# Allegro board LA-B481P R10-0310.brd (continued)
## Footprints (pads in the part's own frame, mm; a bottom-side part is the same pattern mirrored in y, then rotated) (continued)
FIDUCIAL_C40M80
  round 1.016 smd: 1(0,0)
G993P1UF_SOP8
  oval 0.635x1.854 smd: 1(0,0) 2(1.27,0) 3(2.54,0) 4(3.81,0) 5(3.81,5.165) 6(2.54,5.165) 7(1.27,5.165) 8(0,5.165)
G2129TL1U_SC70-6
  oval 0.305x0.711 smd: 1(0,0) 2(0.65,0) 3(1.3,0) 4(1.3,2.15) 5(0.65,2.15) 6(0,2.15)
H_2P8
  round 3.302 hole 2.794: 1(0,0)
H_3P3
  round 3.81 hole 3.302: 1(0,0)
H_3P7
  round 4.216 hole 3.708: 1(0,0)
H_3P7X3P2N
  oval 3.708x3.2 hole 3.708x3.2 unplated: (0,0)
HB_A090420-SAHR21_4P
  oval 0.61x1.499 smd: 1(0,0) 2(1,0) 3(2,0) 4(3,0)
  rect 2.489x2.21 smd: 5(-3,-3.15) 6(6,-3.15)
HB_A823020-SBHR21_30P
  oval 0.305x1.295 smd: 1(0,0) 2(0.8,0) 3(1.6,0) 4(2.4,0) 5(3.2,0) 6(4,0) 7(4.8,0) 8(5.6,0) 9(6.4,0) 10(7.2,0) 11(8,0) 12(8.8,0) 13(9.6,0) 14(10.4,0) 15(11.2,0) 16(12,0) 17(12.8,0) 18(13.6,0) 19(14.4,0) 20(15.2,0) 21(16,0) 22(16.8,0) 23(17.6,0) 24(18.4,0) 25(19.2,0) 26(20,0) 27(20.8,0) 28(21.6,0) 29(22.4,0) 30(23.2,0)
  rect 1.803x2.21 smd: 31(25.55,-5.65) 32(-2.35,-5.65)
IP4292CZ10-TBR_XSON10_2P5X1
  oval 0.254x0.889 smd: 1(0,0)
  oval 0.254x0.838 smd: 2(0.5,-0.025) 3(1,-0.025) 4(1.5,-0.025) 5(2,-0.025) 6(2,1.125) 7(1.5,1.125) 8(1,1.125) 9(0.5,1.125) 10(0,1.125)
ISL95833HRTZ-T_TQFN32_4X4
  oval 0.203x0.914 smd: 1(0,0) 2(0.4,0) 3(0.8,0) 4(1.2,0) 5(1.6,0) 6(2,0) 7(2.4,0) 8(2.8,0) 17(2.8,4.077) 18(2.4,4.077) 19(2,4.077) 20(1.6,4.077) 21(1.2,4.077) 22(0.8,4.077) 23(0.4,4.077) 24(0,4.077)
  oval 0.914x0.203 smd: 9(3.438,0.639) 10(3.438,1.039) 11(3.438,1.438) 12(3.438,1.838) 13(3.438,2.239) 14(3.438,2.639) 15(3.438,3.039) 16(3.438,3.438) 25(-0.639,3.438) 26(-0.639,3.039) 27(-0.639,2.639) 28(-0.639,2.239) 29(-0.639,1.838) 30(-0.639,1.438) 31(-0.639,1.039) 32(-0.639,0.639)
  rect 2.692x2.692 smd: 33(1.4,2.039)
JUMP_43X39
  custom 0.191x0.191 smd: 1(0,0) 2(0.914,0)
JUMP_43X79
  custom 0.188x0.188 smd: 1(0,0) 2(1.1,0)
JUMP_43X118
  custom 0.187x0.187 smd: 1(0,0) 2(1.1,0)
KB9012QF-A2_LQFP128_14X14
  oval 0.203x1.753 smd: 1(0,0) 2(0.4,0) 3(0.8,0) 4(1.2,0) 5(1.6,0) 6(2,0) 7(2.4,0) 8(2.8,0) 9(3.2,0) 10(3.6,0) 11(4,0) 12(4.4,0) 13(4.8,0) 14(5.2,0) 15(5.6,0) 16(6,0) 17(6.4,0) 18(6.8,0) 19(7.2,0) 20(7.6,0) 21(8,0) 22(8.4,0) 23(8.8,0) 24(9.2,0) 25(9.6,0) 26(10,0) 27(10.4,0) 28(10.8,0) 29(11.2,0) 30(11.6,0) 31(12,0) 32(12.4,0) 65(12.4,15.654) 66(12,15.654) 67(11.6,15.654) 68(11.2,15.654) 69(10.8,15.654) 70(10.4,15.654) 71(10,15.654) 72(9.6,15.654) 73(9.2,15.654) 74(8.8,15.654) 75(8.4,15.654) 76(8,15.654) 77(7.6,15.654) 78(7.2,15.654) 79(6.8,15.654) 80(6.4,15.654) 81(6,15.654) 82(5.6,15.654) 83(5.2,15.654) 84(4.8,15.654) 85(4.4,15.654) 86(4,15.654) 87(3.6,15.654) 88(3.2,15.654) 89(2.8,15.654) 90(2.4,15.654) 91(2,15.654) 92(1.6,15.654) 93(1.2,15.654) 94(0.8,15.654) 95(0.4,15.654) 96(0,15.654)
  oval 1.753x0.203 smd: 33(14.027,1.627) 34(14.027,2.027) 35(14.027,2.427) 36(14.027,2.827) 37(14.027,3.227) 38(14.027,3.627) 39(14.027,4.027) 40(14.027,4.427) 41(14.027,4.827) 42(14.027,5.227) 43(14.027,5.627) 44(14.027,6.027) 45(14.027,6.427) 46(14.027,6.827) 47(14.027,7.227) 48(14.027,7.627) 49(14.027,8.027) 50(14.027,8.427) 51(14.027,8.827) 52(14.027,9.227) 53(14.027,9.627) 54(14.027,10.027) 55(14.027,10.427) 56(14.027,10.827) 57(14.027,11.227) 58(14.027,11.627) 59(14.027,12.027) 60(14.027,12.427) 61(14.027,12.827) 62(14.027,13.227) 63(14.027,13.627) 64(14.027,14.027) 97(-1.627,14.027) 98(-1.627,13.627) 99(-1.627,13.227) 100(-1.627,12.827) 101(-1.627,12.427) 102(-1.627,12.027) 103(-1.627,11.627) 104(-1.627,11.227) 105(-1.627,10.827) 106(-1.627,10.427) 107(-1.627,10.027) 108(-1.627,9.627) 109(-1.627,9.227) 110(-1.627,8.827) 111(-1.627,8.427) 112(-1.627,8.027) 113(-1.627,7.627) 114(-1.627,7.227) 115(-1.627,6.827) 116(-1.627,6.427) 117(-1.627,6.027) 118(-1.627,5.627) 119(-1.627,5.227) 120(-1.627,4.827) 121(-1.627,4.427) 122(-1.627,4.027) 123(-1.627,3.627) 124(-1.627,3.227) 125(-1.627,2.827) 126(-1.627,2.427) 127(-1.627,2.027) 128(-1.627,1.627)
KC_FBMA-L11-160808-800LMT_2P
  rect 0.889x1.092 smd: 1(0,0) 2(1.5,0)
KC_FBMA-L11-201209-221LMA30_2P
  rect 0.838x1.397 smd: 1(0,0) 2(1.65,0)
KC_WCM-2012HS-900T_4P
  rect 0.889x0.406 smd: 1(0,0) 2(1.7,0) 3(1.7,-0.8) 4(0,-0.8)
L03ESDL5V0CG3-2_SOT-523-3
  oval 0.406x0.787 smd: 1(0,0) 2(-0.5,-1.4) 3(0.5,-1.4)
L30ESDL5V0C3-2_SOT23-3
  oval 1.016x1.524 smd: 1(0,0) 2(0.965,2.083) 3(-0.965,2.083)
L_4X4X2_F_2P
  rect 1.194x3.708 smd: 1(0,0) 2(2.8,0)
L_5X5X3_M_2P
  rect 2.159x2.794 smd: 1(0,0) 2(4.35,0)
L_7X7X3_M_2P
  rect 2.362x3.505 smd: 1(0,0) 2(6.05,0)
LCN_DAN06-K4406-0102_204P
  round 1.6 hole 1.6 unplated: (-1.75,4.1)
  round 1.092 hole 1.092 unplated: (65.05,4.1)
  oval 0.356x2.007 smd: 1(0,0) 2(0.3,8.2) 3(0.6,0) 4(0.9,8.2) 5(1.2,0) 6(1.5,8.2) 7(1.8,0) 8(2.1,8.2) 9(2.4,0) 10(2.7,8.2) 11(3,0) 12(3.3,8.2) 13(3.6,0) 14(3.9,8.2) 15(4.2,0) 16(4.5,8.2) 17(4.8,0) 18(5.1,8.2) 19(5.4,0) 20(5.7,8.2) 21(6,0) 22(6.3,8.2) 23(6.6,0) 24(6.9,8.2) 25(7.2,0) 26(7.5,8.2) 27(7.8,0) 28(8.1,8.2) 29(8.4,0) 30(8.7,8.2) 31(9,0) 32(9.3,8.2) 33(9.6,0) 34(9.9,8.2) 35(10.2,0) 36(10.5,8.2) 37(10.8,0) 38(11.1,8.2) 39(11.4,0) 40(11.7,8.2) 41(12,0) 42(12.3,8.2) 43(12.6,0) 44(12.9,8.2) 45(13.2,0) 46(13.5,8.2) 47(13.8,0) 48(14.1,8.2) 49(14.4,0) 50(14.7,8.2) 51(15,0) 52(15.3,8.2) 53(15.6,0) 54(15.9,8.2) 55(16.2,0) 56(16.5,8.2) 57(16.8,0) 58(17.1,8.2) 59(17.4,0) 60(17.7,8.2) 61(18,0) 62(18.3,8.2) 63(18.6,0) 64(18.9,8.2) 65(19.2,0) 66(19.5,8.2) 67(19.8,0) 68(20.1,8.2) 69(20.4,0) 70(20.7,8.2) 71(21,0) 72(21.3,8.2) 73(24,0) 74(24.3,8.2) 75(24.6,0) 76(24.9,8.2) 77(25.2,0) 78(25.5,8.2) 79(25.8,0) 80(26.1,8.2) 81(26.4,0) 82(26.7,8.2) 83(27,0) 84(27.3,8.2) 85(27.6,0) 86(27.9,8.2) 87(28.2,0) 88(28.5,8.2) 89(28.8,0) 90(29.1,8.2) 91(29.4,0) 92(29.7,8.2) 93(30,0) 94(30.3,8.2) 95(30.6,0) 96(30.9,8.2) 97(31.2,0) 98(31.5,8.2) 99(31.8,0) 100(32.1,8.2) 101(32.4,0) 102(32.7,8.2) 103(33,0) 104(33.3,8.2) 105(33.6,0) 106(33.9,8.2) 107(34.2,0) 108(34.5,8.2) 109(34.8,0) 110(35.1,8.2) 111(35.4,0) 112(35.7,8.2) 113(36,0) 114(36.3,8.2) 115(36.6,0) 116(36.9,8.2) 117(37.2,0) 118(37.5,8.2) 119(37.8,0) 120(38.1,8.2) 121(38.4,0) 122(38.7,8.2) 123(39,0) 124(39.3,8.2) 125(39.6,0) 126(39.9,8.2) 127(40.2,0) 128(40.5,8.2) 129(40.8,0) 130(41.1,8.2) 131(41.4,0) 132(41.7,8.2) 133(42,0) 134(42.3,8.2) 135(42.6,0) 136(42.9,8.2) 137(43.2,0) 138(43.5,8.2) 139(43.8,0) 140(44.1,8.2) 141(44.4,0) 142(44.7,8.2) 143(45,0) 144(45.3,8.2) 145(45.6,0) 146(45.9,8.2) 147(46.2,0) 148(46.5,8.2) 149(46.8,0) 150(47.1,8.2) 151(47.4,0) 152(47.7,8.2) 153(48,0) 154(48.3,8.2) 155(48.6,0) 156(48.9,8.2) 157(49.2,0) 158(49.5,8.2) 159(49.8,0) 160(50.1,8.2) 161(50.4,0) 162(50.7,8.2) 163(51,0) 164(51.3,8.2) 165(51.6,0) 166(51.9,8.2) 167(52.2,0) 168(52.5,8.2) 169(52.8,0) 170(53.1,8.2) 171(53.4,0) 172(53.7,8.2) 173(54,0) 174(54.3,8.2) 175(54.6,0) 176(54.9,8.2) 177(55.2,0) 178(55.5,8.2) 179(55.8,0) 180(56.1,8.2) 181(56.4,0) 182(56.7,8.2) 183(57,0) 184(57.3,8.2) 185(57.6,0) 186(57.9,8.2) 187(58.2,0) 188(58.5,8.2) 189(58.8,0) 190(59.1,8.2) 191(59.4,0) 192(59.7,8.2) 193(60,0) 194(60.3,8.2) 195(60.6,0) 196(60.9,8.2) 197(61.2,0) 198(61.5,8.2) 199(61.8,0) 200(62.1,8.2) 201(62.4,0) 202(62.7,8.2) 203(63,0) 204(63.3,8.2)
  rect 3.505x4.597 smd: 205(-1.15,16.1) 206(64.45,16.1)
LED_12-21C-T3D-CM2P1B18X-2C_3P
  rect 0.991x0.787 smd: 1(0,0) 2(-2.8,0)
  rect 0.991x0.61 smd: 3(-1.4,0.4)
LED_HT-210UD5-BP5_3P
  rect 1.194x0.787 smd: 1(0,0) 2(3,0)
  rect 0.889x0.991 smd: 3(1.5,0.5)
LOTES_AAA-BAT-054-K01_2P
  round 0.787 hole 0.787 unplated: (-14.5,-8)
  round 1.194 hole 1.194 unplated: (-14.5,8)
  rect 2.007x3.988 smd: 1(0,0) 2(-30.1,0)
LOTES_ABA-HDM-022-K01_19P
  round 0.813 hole 0.559: 1(0,0) 2(-0.5,-1.55) 3(-1,0) 4(-1.5,-1.55) 5(-2,0) 6(-2.5,-1.55) 7(-3,0) 8(-3.5,-1.55) 9(-4,0) 10(-4.5,-1.55) 11(-5,0) 12(-5.5,-1.55) 13(-6,0) 14(-6.5,-1.55) 15(-7,0) 16(-7.5,-1.55) 17(-8,0) 18(-8.5,-1.55) 19(-9,0)
  oval 1.702x2.794 hole 1.092x2.21: 20(4.55,5.38) 21(4.55,-1.72) 22(-13.55,-1.72) 23(-13.55,5.38)
MC74VHC1G08DFT2G_SC70-5
  oval 0.381x0.711 smd: 1(0,0) 2(0.65,0) 3(1.3,0) 4(1.3,1.9) 5(0,1.9)
MDS1525URH_SO8
  oval 0.635x1.854 smd: 1(0,0) 2(1.27,0) 3(2.54,0) 4(3.81,0) 5(3.81,5.165) 6(2.54,5.165) 7(1.27,5.165) 8(0,5.165)
MDV1527URH_POWERDFN33-8-5
  oval 0.406x0.61 smd: 1(0,0) 2(0.65,0) 3(1.3,0) 4(1.95,0)
  custom 0.65x0.65 smd: 5(0.975,1.475)
MDV1528URH_PDFN33-8-5
  oval 0.406x0.61 smd: 1(0,0) 2(0.65,0) 3(1.3,0) 4(1.95,0)
  custom 0.65x0.65 smd: 5(0.975,1.475)
MESS138W-G_SOT323-3
  oval 0.711x0.889 smd: 1(0,0) 2(-0.65,-1.9) 3(0.65,-1.9)
MOLEX_52435-2671_26P-T
  oval 0.305x0.787 smd: 1(0,0) 2(0.5,0) 3(1,0) 4(1.5,0) 5(2,0) 6(2.5,0) 7(3,0) 8(3.5,0) 9(4,0) 10(4.5,0) 11(5,0) 12(5.5,0) 13(6,0) 14(6.5,0) 15(7,0) 16(7.5,0) 17(8,0) 18(8.5,0) 19(9,0) 20(9.5,0) 21(10,0) 22(10.5,0) 23(11,0) 24(11.5,0) 25(12,0) 26(12.5,0)
  custom 0.597x0.597 smd: 27(-2.45,-1.925) 28(14.95,-1.925)
MURAT_BLM15AG601SN1D_2P
  oval 0.457x0.508 smd: 1(0,0) 2(0.85,0)
MURAT_BLM15BB221SN1D_2P
  rect 0.508x0.762 smd: 1(0,0) 2(0.75,0)
MURAT_BLM15BX102SN1D_2P
  rect 0.457x0.508 smd: 1(0,0) 2(0.85,0)
MURAT_DLW21SN670HQ2L_4P
  rect 0.889x0.406 smd: 1(0,0) 2(1.7,0) 3(1.7,0.8) 4(0,0.8)
PANAS_ETQP4LR15AFM_4P
  custom 0.686x0.686 smd: 1(0,0) 4(8.357,0)
  rect 2.21x0.508 smd: 2(1.448,0) 3(6.909,0)
PESD5V0U2BT_SOT23-3
  oval 1.016x1.524 smd: 1(0,0) 2(0.965,2.083) 3(-0.965,2.083)
PS_HPF10052-06M000R_6P
  oval 0.305x1.499 smd: 1(0,0) 2(1,0) 3(2,0) 4(3,0) 5(4,0) 6(5,0)
  rect 2.489x1.905 smd: 7(7.65,-3.4) 8(-2.65,-3.4)
R0402_0OHM
  rect 0.508x0.559 smd: 1(0,0) 2(0.914,0)
R0603_0OHM
  rect 0.635x0.889 smd: 1(0,0) 2(1.397,0)
R0805_0OHM
  rect 0.813x1.397 smd: 1(0,0) 2(1.702,0)
R_0402
  rect 0.508x0.559 smd: 1(0,0) 2(0.914,0)
R_0603
  rect 0.635x0.889 smd: 1(0,0) 2(1.397,0)
R_0805
  rect 0.813x1.397 smd: 1(0,0) 2(1.702,0)
R_1206
  rect 1.016x1.651 smd: 1(0,0) 2(2.667,0)
R_1206_4P-D
  custom 0.445x0.445 smd: 1(0,0) 4(5.004,0)
  custom 0.114x0.114 smd: 2(1.194,0) 3(3.81,0)
RB751V40_SC76-2
  rect 0.61x0.61 smd: 1(0,0) 2(2.2,0)
RB751V-40_SOD323-2
  rect 0.787x0.889 smd: 1(0,0) 2(2.14,0)
RHU002N06_SOT323-3
  oval 0.813x0.914 smd: 1(0,0) 2(0.65,1.6) 3(-0.65,1.6)
RP_0804_8P4R
  oval 0.66x0.254 smd: 1(0,0) 2(0,-0.5) 3(0,-1) 4(0,-1.5) 5(1.15,-1.5) 6(1.15,-1) 7(1.15,-0.5) 8(1.15,0)
RT8207MZQW_WQFN20_3X3
  oval 0.203x0.889 smd: 1(0,0) 2(0.4,0) 3(0.8,0) 4(1.2,0) 5(1.6,0) 11(1.6,3.1) 12(1.2,3.1) 13(0.8,3.1) 14(0.4,3.1) 15(0,3.1)
  oval 0.889x0.203 smd: 6(2.35,0.75) 7(2.35,1.15) 8(2.35,1.55) 9(2.35,1.95) 10(2.35,2.35) 16(-0.75,2.35) 17(-0.75,1.95) 18(-0.75,1.55) 19(-0.75,1.15) 20(-0.75,0.75)
  rect 1.702x1.702 smd: 21(0.8,1.55)
RTD2132S-GR_QFN32_5X5
  oval 0.254x1.041 smd: 1(0,0) 2(0.5,0) 3(1,0) 4(1.5,0) 5(2,0) 6(2.5,0) 7(3,0) 8(3.5,0) 17(3.5,4.95) 18(3,4.95) 19(2.5,4.95) 20(2,4.95) 21(1.5,4.95) 22(1,4.95) 23(0.5,4.95) 24(0,4.95)
  oval 1.041x0.254 smd: 9(4.225,0.725) 10(4.225,1.225) 11(4.225,1.725) 12(4.225,2.225) 13(4.225,2.725) 14(4.225,3.225) 15(4.225,3.725) 16(4.225,4.225) 25(-0.725,4.225) 26(-0.725,3.725) 27(-0.725,3.225) 28(-0.725,2.725) 29(-0.725,2.225) 30(-0.725,1.725) 31(-0.725,1.225) 32(-0.725,0.725)
  rect 3.353x3.353 smd: 33(1.75,2.475)
RTL8106E-CG_QFN32_4X4
  oval 0.203x0.838 smd: 1(0,0) 2(0.4,0) 3(0.8,0) 4(1.2,0) 5(1.6,0) 6(2,0) 7(2.4,0) 8(2.8,0) 17(2.8,4.15) 18(2.4,4.15) 19(2,4.15) 20(1.6,4.15) 21(1.2,4.15) 22(0.8,4.15) 23(0.4,4.15) 24(0,4.15)
  oval 0.838x0.203 smd: 9(3.475,0.675) 10(3.475,1.075) 11(3.475,1.475) 12(3.475,1.875) 13(3.475,2.275) 14(3.475,2.675) 15(3.475,3.075) 16(3.475,3.475) 25(-0.675,3.475) 26(-0.675,3.075) 27(-0.675,2.675) 28(-0.675,2.275) 29(-0.675,1.875) 30(-0.675,1.475) 31(-0.675,1.075) 32(-0.675,0.675)
  rect 2.692x2.692 smd: 33(1.4,2.075)
RTS5179-GR_QFN24_4X4
  oval 0.254x0.889 smd: 1(0,0) 2(0.5,0) 3(1,0) 4(1.5,0) 5(2,0) 6(2.5,0) 13(2.5,4.1) 14(2,4.1) 15(1.5,4.1) 16(1,4.1) 17(0.5,4.1) 18(0,4.1)
  oval 0.889x0.254 smd: 7(3.3,0.8) 8(3.3,1.3) 9(3.3,1.8) 10(3.3,2.3) 11(3.3,2.8) 12(3.3,3.3) 19(-0.8,3.3) 20(-0.8,2.8) 21(-0.8,2.3) 22(-0.8,1.8) 23(-0.8,1.3) 24(-0.8,0.8)
  rect 2.261x2.261 smd: 25(1.25,2.05)
SANTA_130456-311_8P
  round 1.295 hole 0.889: 1(0,0) 2(1.02,1.1) 3(2.04,0) 4(3.06,1.1) 5(4.08,0) 6(5.1,1.1) 7(6.12,0) 8(7.14,1.1)
  oval 1.753x3.15 hole 0.991x2.388: 9(-5.83,-12) 10(12.97,-12)
SANTA_193202-1_22P
  round 1.194 hole 1.194 unplated: (-31.47,-1.84) (-0.28,-1.84)
  round 1.092 hole 0.787: 1(0,0) 2(-1.27,0) 3(-2.54,0) 4(-3.81,0) 5(-5.08,0) 6(-6.35,0) 7(-7.62,0) 8(-13.97,0) 9(-15.24,0) 10(-16.51,0) 11(-17.78,0) 12(-19.05,0) 13(-20.32,0) 14(-21.59,0) 15(-22.86,0) 16(-24.13,0) 17(-25.4,0) 18(-26.67,0) 19(-27.94,0) 20(-29.21,0) 21(-30.48,0) 22(-31.75,0)
  oval 1.803x3.2 hole 0.991x2.388: 23(2.2,-0.73) 24(-33.95,-0.73)
SANTA_202801-1_13P
  round 1.194 hole 1.194 unplated: (-19.78,-1.75) (1.02,-1.75)
  round 1.067 hole 0.711: 1(0,0) 2(-1.27,0) 3(-2.54,0) 4(-3.81,0) 5(-5.08,0) 6(-6.35,0) 7(-7.62,0)
  round 1.016 hole 0.61: 8(-13.83,1) 9(-14.83,0) 10(-15.83,1) 11(-16.83,0) 12(-17.83,1) 13(-18.83,0)
  custom 1.499x1.499 hole 2.311: 14(3.77,-0.75) 15(-22.53,-0.75)
SHORTPADS
  custom 0.19x0.19 smd: 1(-0.483,0) 2(0.483,0)
SI3456BDV-T1-E3_TSOP6
  oval 0.508x1.448 smd: 1(0,0) 2(1,0) 3(2,0) 4(2,2.425) 5(1,2.425) 6(0,2.425)
SI3457CDV-T1-GE3_TSOP6
  oval 0.508x1.422 smd: 1(0,0) 2(0.95,0) 3(1.9,0) 4(1.9,2.44) 5(0.95,2.44) 6(0,2.44)
SI4459ADY-T1-GE3_SO8
  oval 0.635x1.727 smd: 1(0,0) 2(1.27,0) 3(2.54,0) 4(3.81,0) 5(3.81,5.285) 6(2.54,5.285) 7(1.27,5.285) 8(0,5.285)
SINGA_2SJ-E960-001F_6P
  oval 1.194x1.803 hole 0.61x1.194: 1(0,0) 2(11.8,0) 3(0,-9.65) 4(11.8,-2.5) 5(11.8,-9.65) 6(0,-5.62)
SLG3NB274VTR_TQFN16_2X3
  oval 0.203x0.914 smd: 1(0,-0.013) 2(0.4,-0.013) 3(0.8,-0.013) 4(1.2,-0.013) 5(1.6,-0.013) 6(2,-0.013) 7(2.4,-0.013) 9(2.4,2.063) 10(2,2.063) 11(1.6,2.063) 12(1.2,2.063) 13(0.8,2.063) 14(0.4,2.063) 15(0,2.063)
  oval 0.914x0.203 smd: 8(2.738,1.025) 16(-0.338,1.025)
  rect 1.905x0.889 smd: 17(1.2,1.025)
SN74LVC1G06DCKR_SC70-5
  oval 0.381x0.864 smd: 1(0,0) 2(0.65,0) 3(1.3,0) 4(1.3,1.74) 5(0,1.74)
SN74LVC1G07DCKR_SC70-5
  oval 0.381x0.864 smd: 1(0,0) 2(0.65,0) 3(1.3,0) 4(1.3,1.74) 5(0,1.74)
STARC_107K40-000001-G2_40P
  round 1.092 hole 1.092 unplated: (-2.3,-1.95) (21.8,-1.95)
  oval 0.254x1.295 smd: 1(0,0) 2(0.5,0) 3(1,0) 4(1.5,0) 5(2,0) 6(2.5,0) 7(3,0) 8(3.5,0) 9(4,0) 10(4.5,0) 11(5,0) 12(5.5,0) 13(6,0) 14(6.5,0) 15(7,0) 16(7.5,0) 17(8,0) 18(8.5,0) 19(9,0) 20(9.5,0) 21(10,0) 22(10.5,0) 23(11,0) 24(11.5,0) 25(12,0) 26(12.5,0) 27(13,0) 28(13.5,0) 29(14,0) 30(14.5,0) 31(15,0) 32(15.5,0) 33(16,0) 34(16.5,0) 35(17,0) 36(17.5,0) 37(18,0) 38(18.5,0) 39(19,0) 40(19.5,0)
  rect 1.549x3.404 smd: 41(-4.125,-5.85) 42(23.625,-5.85)
  rect 2.007x6.198 smd: 43(0.5,-7.65) 44(6,-7.65) 45(13.5,-7.65) 46(19,-7.65)
SUYIN_200028MR009G502ZL_9P
  round 1.499 hole 0.991: 1(0,0) 2(2,0) 3(4,0) 4(6,0) 5(8,0) 6(10,0) 7(12,0) 8(14,0) 9(16,0)
  oval 1.499x3.302 hole 0.991x2.794: 10(19.125,0) 11(-3.125,0)
SW_SMT1-05-A_4P
  rect 0.61x0.991 smd: 1(0,0) 2(0,-4.4) 3(3.7,0) 4(3.7,-4.4)
  rect 0.457x0.991 smd: 5(-0.675,-2.2) 6(4.375,-2.2)
SY6288C20AAC_SOT23-5
  oval 0.559x0.787 smd: 1(0,0) 2(0.95,0) 3(1.9,0) 4(1.9,2.4) 5(0,2.4)
SY6288D20AAC_SOT23-5
  oval 0.559x0.787 smd: 1(0,0) 2(0.95,0) 3(1.9,0) 4(1.9,2.4) 5(0,2.4)
SY8032ABC_SOT23-6
  oval 0.61x0.991 smd: 1(0,0) 2(0.95,0) 3(1.9,0) 4(1.9,2.4) 5(0.95,2.4) 6(0,2.4)
T-SOL_143-2300302602_22P_RV
  round 1.194 hole 1.194 unplated: (0.5,-2.69) (20.5,-2.69)
  oval 0.508x1.854 smd: 1(0,0) 2(0.76,0) 3(1.52,0) 4(2.28,0) 5(3.8,0) 6(4.56,0) 7(5.32,0) 8(6.84,0) 9(7.6,0) 10(8.36,0) 11(9.12,0) 12(9.88,0) 13(11.4,0) 14(12.16,0) 15(12.92,0) 16(14.44,0) 17(15.2,0) 18(16.72,0) 19(19,0) 20(19.76,0) 21(20.52,0) 22(21.28,0)
  oval 1.092x2.997 hole 0.508x1.803: 23(-6.6,-23.63) 24(22.7,-23.63)
TAI-T_HCB2012KF-121T50_2P
  rect 0.991x0.991 smd: 1(0,0) 2(2,0)
TAIYO_FBMJ4516HS720NT_2P
  rect 1.549x1.854 smd: 1(0,0) 2(3.95,0)
TOKO_1239AS-H-1R0M-P2_2P
  rect 0.787x2.007 smd: 1(0,0) 2(2,0)
TPC12
  round 0.305 smd: 1(0,0)
TPS22966DPUR_SON14_2X3
  oval 0.203x0.762 smd: 1(0,0) 2(0.4,0) 3(0.8,0) 4(1.2,0) 5(1.6,0) 6(2,0) 7(2.4,0) 8(2.4,2.05) 9(2,2.05) 10(1.6,2.05) 11(1.2,2.05) 12(0.8,2.05) 13(0.4,2.05) 14(0,2.05)
  rect 2.489x0.889 smd: 15(1.2,1.025)
TPS51225CRUKR_QFN20_3X3
  oval 0.203x0.889 smd: 1(0,0) 2(0.4,0) 3(0.8,0) 4(1.2,0) 5(1.6,0) 11(1.6,3.1) 12(1.2,3.1) 13(0.8,3.1) 14(0.4,3.1) 15(0,3.1)
  oval 0.889x0.203 smd: 6(2.35,0.75) 7(2.35,1.15) 8(2.35,1.55) 9(2.35,1.95) 10(2.35,2.35) 16(-0.75,2.35) 17(-0.75,1.95) 18(-0.75,1.55) 19(-0.75,1.15) 20(-0.75,0.75)
  rect 1.702x1.702 smd: 21(0.8,1.55)
TVNST52302AB0_SOT523-3
  oval 0.508x0.559 smd: 1(0,0) 2(-0.5,-1.4) 3(0.5,-1.4)
W25Q64DWSSIG_SO8
  oval 0.635x1.676 smd: 1(0,0) 2(1.27,0) 3(2.54,0) 4(3.81,0) 5(3.81,7.25) 6(2.54,7.25) 7(1.27,7.25) 8(0,7.25)
Y_5YEA12000122IFA2Q3_4P
  rect 1.295x1.194 smd: 1(0,0) 2(2.2,0) 3(2.2,1.7) 4(0,1.7)
Y_7V25000014_4P
  rect 1.397x1.194 smd: 1(0,0) 2(2.2,0) 3(2.2,1.7) 4(0,1.7)
Y_FSX3M-25PM20FDO_4P
  rect 1.397x1.194 smd: 1(0,0) 2(2.2,0) 3(2.2,1.6) 4(0,1.6)
Y_Q13FC135000040_2P
  rect 0.991x1.803 smd: 1(0,0) 2(2.5,0)

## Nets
1.0VS_GATE: C1131.1 Q70.1 R1061.1 U60.4
1.8VS_ON: C1125.2 R1055.1 U59.3
1.35VS_ON: C1128.2 R1056.1 U59.5
3VS_ON: C980.1 R927.1 U11.3
5VS_ON: C979.2 R926.2 U11.5
+0.675VS: CD24.1 CD25.1 CD26.1 CD27.1 CD28.1 CD29.1 JDIMM1.203 JDIMM1.204 PJP202.2 R2314.1
+0.675VSP: PC208.1 PC209.1 PJP202.1 PU200.2 PU200.20
+1.0VALW: C1034.2 C1035.2 C1036.2 C1037.2 C1039.2 C1074.1 C1129.2 PJP303.2 U60.5 U60.6 U60.7 U60.8 USOC1.B6 USOC1.C3 USOC1.C5 USOC1.U22 USOC1.V18 USOC1.V22 USOC1.Y19
+1.0VALWP: PC308.1 PC310.1 PC311.1 PJP303.1 PL301.2 PR307.1
+1.0VALWP_ON: PC309.1 PR305.1 PR308.2 PU301.1
+1.0VS: C1043.2 C1044.2 C1046.2 C1047.2 C1048.2 C1049.2 C1050.2 C1052.2 C1056.2 C1057.2 C1059.2 C1060.2 C1061.2 C1062.2 C1064.2 C1066.2 C1068.2 C1069.2 C1070.2 C1071.2 C1072.2 C1130.2 PC523.1 PR525.2 PR526.2 PR527.2 R1052.2 RC15.2 RC27.1 U60.1 U60.2 U60.3 USOC1.AA36 USOC1.AD35 USOC1.AF16 USOC1.AF18 USOC1.AF21 USOC1.AF35 USOC1.AF36 USOC1.AG21 USOC1.AJ18 USOC1.AJ36 USOC1.AK18 USOC1.AK19 USOC1.AK21 USOC1.AK35 USOC1.AK36 USOC1.AM16 USOC1.AM18 USOC1.AM21 USOC1.AN18 USOC1.AN19 USOC1.AN21 USOC1.AN25 USOC1.AN29 USOC1.AN30 USOC1.BJ6 USOC1.G1 USOC1.M14 USOC1.U18 USOC1.U19 USOC1.V24 USOC1.V32 USOC1.Y18 USOC1.Y22 USOC1.Y24 USOC1.Y35 USOC1.Y36
+1.0VS_R: Q71.1 R1052.1
+1.05V_PGOOD: T210.1(TP-1) UE1.122
+1.05VS: C1038.1 C1040.1 C1041.1 C1042.1 CG2.1 PJP301.2 R2315.1 RC100.2 UG1.3 USOC1.AA33 USOC1.AF33 USOC1.AG33 USOC1.AG35 USOC1.U33 USOC1.U35 USOC1.V33
+1.5VS: C1058.1 JMINI.6 JMINI.28 JMINI.48 PJP405.2 RA8.1 USOC1.AM32
+1.05VS_SOC: RC100.1 USOC1.AC32 USOC1.Y32
+1.5VSP: PC413.1 PC414.1 PJP405.1 PR410.1 PU402.3 PU402.4
+1.05VSP: PC301.1 PC302.1 PC303.1 PJP301.1 PL300.2 PR302.1
+1.05VSP_ON: PC304.1 PR300.2 PR303.1 PU300.1
+1.8VALW: C182.1 C1045.1 C1145.2 JDB1.16 PJP401.2 PJP404.1 R3.1 R4.1 R5.2 R6.1 R7.1 R17.1 RC21.1 RC25.1 RC44.1 RC46.1 RC61.1 RC62.1 RC63.1 RC64.1 RC65.1 RC99.2 RP65.5 RP65.6 RP65.7 RP65.8 RP66.3 RP66.4 U59.1 U59.2 U64.1 USOC1.AA18 USOC1.N20 USOC1.U24 USOC1.U25 USOC1.V25
+1.8VALWP: PC401.1 PC402.1 PC403.1 PJP401.1 PL400.2 PR402.1
+1.8VGS: CG1.1 UG1.11
+1.8VS: C1051.1 C1053.1 C1054.1 C1055.1 C1147.1 JP38.2 Q57.2 Q58.2 QC2.2 QC3.2 QC4.2 R8.1 R15.1 R376.1 R377.1 RC8.2 RC10.1 RC16.1 RC17.1 RC18.1 RC43.1 RP15.3 RP15.4 RP63.5 RP63.6 RP63.7 RP63.8 RP68.5 RP68.6 RP68.7 UC4.5 UC10.5 USOC1.AM30 USOC1.AN32 USOC1.U38
+1.8VS_OUT: C1124.2 JP38.1 U59.13 U59.14
+1.8VSP_ON: PC404.1 PR400.2 PR403.1 PU400.1
+1.35V: C1146.2 CD4.1 CD5.1 CD6.1 CD7.1 CD8.1 CD9.1 CD10.1 CD11.1 CD12.1 CD13.1 CD14.1 CD15.1 CD16.1 CD17.1 CD18.1 CD19.1 CD20.1 CD62.2 JDIMM1.75 JDIMM1.76 JDIMM1.81 JDIMM1.82 JDIMM1.87 JDIMM1.88 JDIMM1.93 JDIMM1.94 JDIMM1.99 JDIMM1.100 JDIMM1.105 JDIMM1.106 JDIMM1.111 JDIMM1.112 JDIMM1.117 JDIMM1.118 JDIMM1.123 JDIMM1.124 JP14.2 JP15.2 PC902.1 PC904.1 PC906.1 PC908.1 PJP201.2 R1027.1 R1029.1 RC6.1 RD3.1 U59.6 U59.7
+1.35V_SOC: CC29.2 CC30.2 CC31.2 CC32.2 CC33.1 CC34.1 JP14.1 JP15.1 RC54.2 USOC1.A48 USOC1.AK38 USOC1.AM38 USOC1.AV41 USOC1.AV42 USOC1.BB46 USOC1.BD49 USOC1.BD52 USOC1.BD53 USOC1.BF44 USOC1.BG51 USOC1.BJ48 USOC1.C51 USOC1.D44 USOC1.F49 USOC1.F52 USOC1.F53 USOC1.H46 USOC1.M41 USOC1.M42 USOC1.V38 USOC1.Y38
+1.35VP: PC201.1 PJP201.1 PL200.1 PR204.2 PR210.1 PU200.5 PU200.19
+1.35VS: C1148.1 CC38.1 CC39.1 CC40.1 CC41.1 CC42.1 CC43.1 CC44.1 CC45.1 CC46.1 CC47.1 JP39.2 L1.2 RC30.1 USOC1.AA25 USOC1.AD36 USOC1.AF19 USOC1.AG18 USOC1.AG19 USOC1.AG32 USOC1.AJ19 USOC1.U36 USOC1.V36
+1.35VS_OUT: C1126.2 JP39.1 U59.8 U59.9
+3V_HUB: C1119.1 R1047.1 R1049.1 R1050.1 R1051.1 U58.20
+3V_WLAN: CM40.1 CM43.1 CM46.2 CM47.1 CM48.2 JMINI.2 JMINI.24 JMINI.39 JMINI.41 JMINI.52 RM25.2 RM26.2
+3VALW: C1143.2 C2316.1 C2318.1 CG10.1 JP4.2 JP5.2 JPWR.1 PJP101.2 PJP302.1 PR4.2 PR7.2 PR510.1 PR530.2 R13.1 R14.1 R1022.2 RA10.1 RE6.1 RL40.1 U11.1 U11.2 UC7.5 UG1.2
+3VALW_EC: CE1.1 CE2.1 CE5.2 CE6.2 LE1.1 R18.1 R20.1 R488.1 R489.1 R696.2 R697.2 RE3.2 RE4.2 RE6.2 RE8.2 RE11.2 RE71.1 RP36.5 RP36.6 U61.5 U62.5 U63.5 U64.6 UE1.9 UE1.22 UE1.33 UE1.96 UE1.125
+3VALW_SOC: C1063.1 C1065.1 C1067.1 R1022.1 USOC1.N18 USOC1.N22 USOC1.P18
+3VALW_UL2: CL38.1 CL39.1 JP3.2 JP5.1 UL2.4 UL2.5
+3VALW_UL3: JP4.1 UL3.5
+3VALWP: PC102.1 PC106.1 PJP101.1 PL100.1 PR100.1 PR106.1
+3VLP: CG4.1 JP12.1 PC105.1 PU100.3 R19.1 R21.1 RE4.1 RE49.2 UE1.111 UG1.15
+3VS: C2323.1 C2324.1 CA57.1 CA58.1 CA59.1 CA60.1 CD30.1 CD31.1 CD62.1 CD63.1 CE15.1 CR1.1 CR2.1 CX1.1 CX7.1 JDIMM1.199 JHDD.8 JHDD.9 JLVDS.26 JP36.2 JTP.1 Q14.5 QD18.2 QD19.2 QM30.2 R122.1 R378.1 R1023.2 RA1.1 RA2.1 RA9.1 RA155.2 RC20.1 RC53.1 RC68.1 RD45.1 RD47.1 RE9.1 RE10.1 RE50.1 RL33.1 RM25.1 RM26.1 RM110.1 RP36.7 RP36.8 RP54.5 RP54.6 RP54.7 RP54.8 RS7.1 RT1.1 RV299.1 RX12.1 RX27.1 RX29.1 U65.5 U66.5 UA1.1 UA1.36 UD1.5 UE2.5 UR1.4
+3VS_CAM: JLVDS.29 RX27.2
+3VS_LCDIN: CX9.1 RV299.2 UX1.4 UX1.5
+3VS_OUT: C1138.2 JP36.1 U11.13 U11.14
+3VS_RT: CX10.1 LT1.2 LT2.2 QX6.2 QX6.5 RT1.2 RT17.1 UX2.5
+3VS_SOC: C1073.1 R1023.1 USOC1.AM27 USOC1.AN24 USOC1.AN27
+5V_HDD: CS5.1 CS6.1 CS7.1 JHDD.14 JHDD.15 JHDD.16 JP13.1
+5V_HUB: C1117.1 C1118.1 R1045.2 R1046.1 U58.19
+5V_PVDD: CA53.1 CA54.1 CA55.1 CA56.1 RV54.2 UA1.41 UA1.46
+5V_USB_PWR1: CI1.1 CI2.1 CI40.1 JP8.2 JUSB1.1 RI1.1 RI4.1
+5V_USB_PWR1_R1: RI1.2 UI3.6 UI3.7 UI3.8
+5V_USB_PWR1_R2: RI4.2 UI1.1
+5V_USB_PWR2: CI8.1 CI9.1 CI43.1 JP8.1 JUSB8.1 RI2.1 RI5.1
+5V_USB_PWR2_R1: RI2.2 UI2.6 UI2.7 UI2.8
+5V_USB_PWR2_R2: RI5.2 UI4.1
+5V_USB_PWR3: CI33.1 CI34.1 CI45.1 JUSB7.1 RI3.1 RI6.1
+5V_USB_PWR3_R1: RI3.2 UI6.6 UI6.7 UI6.8
+5V_USB_PWR3_R2: RI6.2 UI5.1
+5VA: CA51.1 CA71.1 RV59.2 UA1.26
+5VALW: C1120.1 C1144.2 C2305.1 C2306.1 CI6.1 CI7.1 CI10.1 CI11.1 CI12.1 CI14.1 CI18.1 LED1.1 LED4.2 PC411.1 PC715.1 PJP100.2 PJP300.1 PJP400.1 PR3.1 PR203.1 PR209.1 PR518.2 PR519.1 PR524.1 PU402.6 PU700.11 R10.1 R1045.1 R1061.2 RD46.1 U11.4 U11.6 U11.7 U59.4 UI1.5 UI2.2 UI2.3 UI3.2 UI3.3 UI4.5 UI5.5 UI6.2 UI6.3
+5VALWP: PC103.1 PC107.2 PJP100.1 PL101.2 PR101.2 PU100.14
+5VS: C2307.1 C2308.1 CE25.1 CS13.1 FX1.2 JP7.1 JP13.2 JP37.2 LED2.2 QS2.1 QS2.2 QS2.5 QS2.6 RE60.1 RV54.1 RV59.1 RX28.1 UE3.1 UE3.2 UI7.5
+5VS_ODD: CS10.1 CS11.1 CS12.1 JODD.9 JODD.10 RS11.1 RS12.1
+5VS_ODD_R1: JP7.2 QS2.4 RS12.2
+5VS_ODD_R2: RS11.2 UI7.1
+5VS_OUT: C1139.2 JP37.1 U11.8 U11.9
+5VS_TOUCH: CX6.1 JTOUCH.1 RX24.1 RX28.2 RX29.2
+AVCC33: CT1.1 CT2.1 CT3.1 LT2.1 UT2.3
+DVCC33: CT4.1 CT5.1 CT6.1 CT7.1 CT8.1 CX50.1 LT1.1 RP56.5 RP56.6 RP56.7 RP56.8 RT2.2 RT20.2 UT2.13 UT2.18
+V18R: CE16.1 UE1.124
+VCC_3IN1: CR7.1 CR8.1 JREAD.4 JREAD.11 UR1.5
B+_3/5V: PC108.1 PC109.1 PC110.1 PC111.1 PL102.2 PQ101.5 PQ102.5 PR111.1
GND: C182.2 C967.1 C976.1 C979.1 C980.2 C1034.1 C1035.1 C1036.1 C1037.1 C1038.2 C1039.1 C1040.2 C1041.2 C1042.2 C1043.1 C1044.1 C1045.2 C1046.1 C1047.1 C1048.1 C1049.1 C1050.1 C1051.2 C1052.1 C1053.2 C1054.2 C1055.2 C1056.1 C1057.1 C1058.2 C1059.1 C1060.1 C1061.1 C1062.1 C1063.2 C1064.1 C1065.2 C1066.1 C1067.2 C1068.1 C1069.1 C1070.1 C1071.1 C1072.1 C1073.2 C1074.2 C1076.2 C1078.2 C1117.2 C1118.2 C1119.2 C1120.2 C1121.2 C1122.1 C1123.1 C1124.1 C1125.1 C1126.1 C1127.1 C1128.1 C1129.1 C1130.1 C1131.2 C1138.1 C1139.1 C1143.1 C1144.1 C1145.1 C1146.1 C1147.2 C1148.2 C2305.2 C2306.2 C2307.2 C2308.2 C2316.2 C2318.2 C2323.2 C2324.2 CA21.2 CA22.2 CA25.1 CA29.2 CA30.2 CA31.2 CA32.2 CA53.2 CA54.2 CA55.2 CA56.2 CA57.2 CA58.2 CA59.2 CA60.2 CA64.1 CA69.2 CC1.2 CC2.2 CC7.2 CC8.1 CC9.2 CC10.2 CC11.2 CC12.2 CC13.2 CC14.2 CC15.2 CC16.2 CC17.2 CC18.2 CC19.2 CC20.1 CC21.2 CC22.2 CC23.2 CC24.1 CC25.2 CC26.2 CC27.2 CC28.2 CC29.1 CC30.1 CC31.1 CC32.1 CC33.2 CC34.2 CC35.2 CC36.2 CC38.2 CC39.2 CC40.2 CC41.2 CC42.2 CC43.2 CC44.2 CC45.2 CC46.2 CC47.2 CC49.2 CC50.2 CC51.2 CC52.2 CC53.2 CC54.2 CC55.2 CC56.2 CC57.2 CC58.2 CC59.2 CC60.2 CC61.2 CC62.2 CC63.2 CC64.2 CC65.2 CD1.2 CD2.2 CD3.2 CD4.2 CD5.2 CD6.2 CD7.2 CD8.2 CD9.2 CD10.2 CD11.2 CD12.2 CD13.2 CD14.2 CD15.2 CD16.2 CD17.2 CD18.2 CD19.2 CD20.2 CD21.2 CD22.2 CD24.2 CD25.2 CD26.2 CD27.2 CD28.2 CD29.2 CD30.2 CD31.2 CD32.2 CD63.2 CE1.2 CE2.2 CE5.1 CE6.1 CE8.2 CE11.2 CE12.2 CE15.2 CE16.2 CE18.1 CE19.2 CE20.2 CE22.2 CE23.2 CE24.2 CE25.2 CE26.2 CE27.2 CE28.2 CE29.2 CE30.2 CE31.2 CE33.2 CE34.2 CE35.2 CE36.2 CG1.2 CG2.2 CG3.2 CG4.2 CG5.2 CG6.2 CG7.2 CG10.2 CI1.2 CI2.2 CI6.2 CI7.2 CI8.2 CI9.2 CI10.2 CI11.2 CI12.2 CI13.2 CI14.2 CI15.2 CI17.2 CI18.2 CI26.2 CI28.2 CI29.2 CI33.2 CI34.2 CI40.2 CI43.2 CI45.2 CL15.2 CL19.2 CL20.2 CL22.2 CL26.2 CL33.2 CL34.2 CL35.2 CL36.1 CL37.1 CL38.2 CL39.2 CL41.1 CLRP1.2 CM40.2 CM43.2 CM46.1 CM47.2 CM48.1 CR1.2 CR2.2 CR3.1 CR4.1 CR5.2 CR6.2 CR7.2 CR8.2 CR9.2 CR10.2 CR11.2 CS5.2 CS6.2 CS7.2 CS10.2 CS11.2 CS12.2 CS13.2 CS16.2 CS17.2 CT1.2 CT2.2 CT3.2 CT4.2 CT5.2 CT6.2 CT7.2 CT8.2 CT9.2 CT10.2 CT11.2 CT12.2 CX1.2 CX2.2 CX3.2 CX5.2 CX6.2 CX7.2 CX8.2 CX9.2 CX10.2 CX11.2 CX20.2 CX21.2 CX22.2 CX23.2 CX24.2 CX25.2 CX26.2 CX27.2 CX28.2 CX29.2 CX30.2 CX50.2 CX51.2 DA10.1 DA12.1 DE1.1 DE3.1 DI1.3 DI1.8 DI2.1 DI8.1 DI9.1 H2.1(TP-1) H4.1(TP-1) H5.1(TP-1) H6.1(TP-1) H7.1(TP-1) H8.1(TP-1) H9.1(TP-1) H10.1(TP-1) H11.1(TP-1) H12.1(TP-1) H16.1(TP-1) H17.1(TP-1) H18.1(TP-1) H31.1(TP-1) H32.1(TP-1) H33.1(TP-1) H34.1(TP-1) JBATT1.2 JDB1.3 JDB1.6 JDB1.9 JDB1.19 JDB1.25 JDB1.27 JDB1.28 JDIMM1.2 JDIMM1.3 JDIMM1.8 JDIMM1.9 JDIMM1.13 JDIMM1.14 JDIMM1.19 JDIMM1.20 JDIMM1.25 JDIMM1.26 JDIMM1.31 JDIMM1.32 JDIMM1.37 JDIMM1.38 JDIMM1.43 JDIMM1.44 JDIMM1.48 JDIMM1.49 JDIMM1.54 JDIMM1.55 JDIMM1.60 JDIMM1.61 JDIMM1.65 JDIMM1.66 JDIMM1.71 JDIMM1.72 JDIMM1.127 JDIMM1.128 JDIMM1.133 JDIMM1.134 JDIMM1.138 JDIMM1.139 JDIMM1.144 JDIMM1.145 JDIMM1.150 JDIMM1.151 JDIMM1.155 JDIMM1.156 JDIMM1.161 JDIMM1.162 JDIMM1.167 JDIMM1.168 JDIMM1.172 JDIMM1.173 JDIMM1.178 JDIMM1.179 JDIMM1.184 JDIMM1.185 JDIMM1.189 JDIMM1.190 JDIMM1.195 JDIMM1.196 JDIMM1.205 JDIMM1.206 JFAN.3 JFAN.4 JFAN.5 JHDD.1 JHDD.4 JHDD.7 JHDD.11 JHDD.12 JHDD.13 JHDD.17 JHDD.19 JHDD.23 JHDD.24 JHDMI.2 JHDMI.5 JHDMI.8 JHDMI.11 JHDMI.17 JHDMI.20 JHDMI.21 JHDMI.22 JHDMI.23 JKB.31 JKB.32 JLAN.9 JLAN.10 JLVDS.3 JLVDS.6 JLVDS.9 JLVDS.12 JLVDS.15 JLVDS.31 JLVDS.41 JLVDS.42 JLVDS.43 JLVDS.44 JLVDS.45 JLVDS.46 JMINI.4 JMINI.9 JMINI.15 JMINI.18 JMINI.21 JMINI.26 JMINI.27 JMINI.29 JMINI.34 JMINI.35 JMINI.40 JMINI.43 JMINI.50 JMINI.53 JMINI.54 JODD.1 JODD.4 JODD.7 JODD.12 JODD.13 JODD.14 JODD.15 JPWR.4 JPWR.5 JPWR.6 JREAD.2 JREAD.9 JREAD.16 JREAD.17 JREAD.21 JREAD.23 JREAD.24 JSPK.5 JSPK.6 JTOUCH.4 JTOUCH.5 JTOUCH.7 JTOUCH.8 JTP.4 JTP.7 JTP.8 JUSB1.4 JUSB1.5 JUSB1.6 JUSB1.7 JUSB1.8 JUSB7.4 JUSB7.5 JUSB7.6 JUSB7.7 JUSB7.8 JUSB8.4 JUSB8.5 JUSB8.6 JUSB8.7 JUSB8.8 LE2.1 PBATT1.1 PBATT1.2 PBATT1.4 PBATT1.10 PBATT1.11 PC1.2 PC2.2 PC3.2 PC4.2 PC5.2 PC6.2 PC8.2 PC9.2 PC102.2 PC103.2 PC105.2 PC108.2 PC109.2 PC110.2 PC111.2 PC114.2 PC115.2 PC116.2 PC117.2 PC118.2 PC201.2 PC203.2 PC204.2 PC205.2 PC206.2 PC208.2 PC209.2 PC210.1 PC211.2 PC212.2 PC213.2 PC214.2 PC215.2 PC300.1 PC302.2 PC303.2 PC304.2 PC305.2 PC306.2 PC307.1 PC308.2 PC309.2 PC311.2 PC400.1 PC402.2 PC403.2 PC404.2 PC405.2 PC411.2 PC412.2 PC414.2 PC415.2 PC501.2 PC502.2 PC503.1 PC508.2 PC509.2 PC510.2 PC511.2 PC512.2 PC516.2 PC517.1 PC518.2 PC519.2 PC520.2 PC521.2 PC522.2 PC523.2 PC525.1 PC526.2 PC533.1 PC534.2 PC535.1 PC702.2 PC703.2 PC704.2 PC705.2 PC706.2 PC707.2 PC708.2 PC710.2 PC711.2 PC712.1 PC714.2 PC715.2 PC716.2 PC717.2 PC718.2 PC719.2 PC720.2 PC721.2 PC723.2 PC725.1 PC726.2 PC727.2 PC901.1 PC902.2 PC903.1 PC904.2 PC905.1 PC906.2 PC907.1 PC908.2 PC909.2 PC911.2 PC913.1 PC914.1 PC915.1 PC916.1 PC917.2 PC918.2 PC919.2 PC920.1 PC921.1 PC922.1 PC923.1 PC924.1 PC925.1 PC926.1 PC927.1 PC928.1 PC929.1 PC930.1 PC931.1 PC932.1 PC933.1 PC934.1 PD1.1 PD2.1 PH501.1 PH502.2 PJP1.2 PL2.2 PQ2.3 PQ3.1 PQ3.4 PQ4.1 PQ4.4 PQ103.1 PQ103.2 PQ103.3 PQ104.1 PQ104.2 PQ104.3 PQ203.1 PQ203.2 PQ203.3 PQ501.5 PQ501.6 PQ501.7 PQ503.5 PQ503.6 PQ503.7 PQ703.1 PQ703.2 PQ703.3 PQ708.3 PQ709.1 PQ709.4 PQ710.1 PQ710.4 PQ711.3 PQ712.3 PQ713.1 PQ713.4 PR5.1 PR19.1 PR21.2 PR26.2 PR102.1 PR103.2 PR104.1 PR105.2 PR116.2 PR206.2 PR303.2 PR304.2 PR305.2 PR309.2 PR403.2 PR404.2 PR411.2 PR412.2 PR508.2 PR514.1 PR529.2 PR534.1 PR715.1 PR716.2 PR728.1 PR729.1 PU100.21 PU200.1 PU200.3 PU200.14 PU200.21 PU300.2 PU301.2 PU400.2 PU402.1 PU500.33 PU700.12 PU700.14 PU700.19 PU700.29 Q8.3 Q14.1 Q14.4 Q50.3 Q70.3 Q71.3 Q2307.3 Q2308.3 Q2309.1 QC1.3 QD20.3 QS3.3 QX1.3 R16.2 R121.2 R122.2 R379.2 R380.2 R1024.2 R1028.1 R1030.1 R1033.2 R1048.2 RA19.2 RA29.2 RA30.2 RA31.2 RA32.2 RA81.1 RC1.1 RC2.1 RC3.1 RC4.1 RC5.1 RC7.1 RC11.2 RC14.2 RC22.1 RC23.1 RC26.2 RC32.1 RC40.2 RC41.1 RC42.1 RC45.1 RC47.1 RC48.2 RC49.1 RC50.1 RC57.2 RC58.2 RC59.2 RC60.1 RC67.2 RD6.1 RD7.1 RD50.2 RD52.2 RE1.1 RE5.1 RE18.2 RE47.1 RL27.1 RL31.1 RL35.1 RM11.1 RP66.1 RP66.2 RR1.2 RS9.2 RT3.1 RT12.1 RT16.2 RT18.2 RT19.2 RX5.1 RX6.2 RX9.2 RX20.2 RX23.2 RX26.2 RX33.2 RX36.2 SW1.1 SW1.2 SW1.5 SW1.6 SW2.1 SW2.2 SW2.5 SW2.6 U11.11 U11.15 U54.3 U57.3 U58.25 U59.11 U59.15 U61.3 U62.3 U63.3 U64.2 U65.3 U66.3 UA1.4 UA1.49 UC4.3 UC5.3 UC7.3 UC8.4 UC10.3 UD1.3 UE1.11 UE1.24 UE1.35 UE1.94 UE1.113 UE2.3 UE3.5 UE3.6 UE3.7 UE3.8 UG1.4 UG1.7 UG1.13 UG1.17 UI1.2 UI2.1 UI2.9 UI3.1 UI3.9 UI4.2 UI5.2 UI6.1 UI6.9 UI7.2 UL1.33 UL2.2 UL3.2 UR1.25 USOC1.A3 USOC1.A5 USOC1.A6 USOC1.A11 USOC1.A15 USOC1.A19 USOC1.A23 USOC1.A27 USOC1.A31 USOC1.A35 USOC1.A39 USOC1.A43 USOC1.A47 USOC1.A49 USOC1.A51 USOC1.A52 USOC1.AA1 USOC1.AA3 USOC1.AA16 USOC1.AA19 USOC1.AA21 USOC1.AA32 USOC1.AA35 USOC1.AA38 USOC1.AA53 USOC1.AB4 USOC1.AB6 USOC1.AB10 USOC1.AB41 USOC1.AB45 USOC1.AB47 USOC1.AB48 USOC1.AB50 USOC1.AB51 USOC1.AC16 USOC1.AC18 USOC1.AC19 USOC1.AC21 USOC1.AC25 USOC1.AC33 USOC1.AC35 USOC1.AC36 USOC1.AC38 USOC1.AD7 USOC1.AD16 USOC1.AD18 USOC1.AD19 USOC1.AD21 USOC1.AD25 USOC1.AD32 USOC1.AD33 USOC1.AD47 USOC1.AE1 USOC1.AE3 USOC1.AE4 USOC1.AE6 USOC1.AE8 USOC1.AE9 USOC1.AE11 USOC1.AE12 USOC1.AE14 USOC1.AE40 USOC1.AE42 USOC1.AE43 USOC1.AE45 USOC1.AE46 USOC1.AE48 USOC1.AE50 USOC1.AE51 USOC1.AE53 USOC1.AF10 USOC1.AF12 USOC1.AF25 USOC1.AF32 USOC1.AF47 USOC1.AG16 USOC1.AG25 USOC1.AG36 USOC1.AG38 USOC1.AH2 USOC1.AH3 USOC1.AH4 USOC1.AH6 USOC1.AH7 USOC1.AH9 USOC1.AH41 USOC1.AH45 USOC1.AH47 USOC1.AH48 USOC1.AH50 USOC1.AH51 USOC1.AJ1 USOC1.AJ3 USOC1.AJ16 USOC1.AJ21 USOC1.AJ25 USOC1.AJ27 USOC1.AJ29 USOC1.AJ30 USOC1.AJ32 USOC1.AJ33 USOC1.AJ35 USOC1.AJ38 USOC1.AJ53 USOC1.AK10 USOC1.AK14 USOC1.AK16 USOC1.AK33 USOC1.AK41 USOC1.AK44 USOC1.AM2 USOC1.AM3 USOC1.AM7 USOC1.AM12 USOC1.AM19 USOC1.AM24 USOC1.AM25 USOC1.AM29 USOC1.AM33 USOC1.AM35 USOC1.AM36 USOC1.AM40 USOC1.AM44 USOC1.AM51 USOC1.AN1 USOC1.AN3 USOC1.AN5 USOC1.AN6 USOC1.AN8 USOC1.AN9 USOC1.AN11 USOC1.AN12 USOC1.AN14 USOC1.AN16 USOC1.AN22 USOC1.AN33 USOC1.AN35 USOC1.AN36 USOC1.AN38 USOC1.AN40 USOC1.AN42 USOC1.AN43 USOC1.AN45 USOC1.AN46 USOC1.AN48 USOC1.AN49 USOC1.AN51 USOC1.AN53 USOC1.AP40 USOC1.AT4 USOC1.AT12 USOC1.AT16 USOC1.AT19 USOC1.AT24 USOC1.AT27 USOC1.AT30 USOC1.AT35 USOC1.AT38 USOC1.AT47 USOC1.AT52 USOC1.AU1 USOC1.AU3 USOC1.AU24 USOC1.AU30 USOC1.AU38 USOC1.AU51 USOC1.AV7 USOC1.AV12 USOC1.AV13 USOC1.AV14 USOC1.AV18 USOC1.AV19 USOC1.AV24 USOC1.AV27 USOC1.AV30 USOC1.AV35 USOC1.AV38 USOC1.AV47 USOC1.AV51 USOC1.AW3 USOC1.AW13 USOC1.AW19 USOC1.AW27 USOC1.AW35 USOC1.AY4 USOC1.AY9 USOC1.AY10 USOC1.AY22 USOC1.AY32 USOC1.AY36 USOC1.AY50 USOC1.B2 USOC1.B52 USOC1.B53 USOC1.BA14 USOC1.BA19 USOC1.BA22 USOC1.BA27 USOC1.BA32 USOC1.BA35 USOC1.BA40 USOC1.BA53 USOC1.BB5 USOC1.BB7 USOC1.BB10 USOC1.BB19 USOC1.BB27 USOC1.BB35 USOC1.BC10 USOC1.BC20 USOC1.BC22 USOC1.BC26 USOC1.BC28 USOC1.BC32 USOC1.BC34 USOC1.BC42 USOC1.BD19 USOC1.BD24 USOC1.BD27 USOC1.BD30 USOC1.BD35 USOC1.BE1 USOC1.BE2 USOC1.BE8 USOC1.BE19 USOC1.BE35 USOC1.BE53 USOC1.BF4 USOC1.BF12 USOC1.BF16 USOC1.BF24 USOC1.BF30 USOC1.BF36 USOC1.BF38 USOC1.BG1 USOC1.BG31 USOC1.BG34 USOC1.BG39 USOC1.BG42 USOC1.BG45 USOC1.BG49 USOC1.BG53 USOC1.BH1 USOC1.BH2 USOC1.BH52 USOC1.BH53 USOC1.BJ2 USOC1.BJ3 USOC1.BJ5 USOC1.BJ7 USOC1.BJ11 USOC1.BJ15 USOC1.BJ19 USOC1.BJ23 USOC1.BJ27 USOC1.BJ31 USOC1.BJ35 USOC1.BJ39 USOC1.BJ43 USOC1.BJ47 USOC1.BJ49 USOC1.BJ51 USOC1.BJ52 USOC1.C1 USOC1.C14 USOC1.C31 USOC1.C34 USOC1.C39 USOC1.C42 USOC1.C45 USOC1.C49 USOC1.C53 USOC1.D12 USOC1.D16 USOC1.D24 USOC1.D30 USOC1.D36 USOC1.D38 USOC1.E1 USOC1.E8 USOC1.E19 USOC1.E35 USOC1.E53 USOC1.F2 USOC1.F5 USOC1.F7 USOC1.F19 USOC1.F24 USOC1.F27 USOC1.F30 USOC1.F35 USOC1.G10 USOC1.G20 USOC1.G22 USOC1.G26 USOC1.G28 USOC1.G32 USOC1.G34 USOC1.G42 USOC1.H19 USOC1.H27 USOC1.H35 USOC1.J1 USOC1.J16 USOC1.J19 USOC1.J22 USOC1.J27 USOC1.J32 USOC1.J35 USOC1.J40 USOC1.J53 USOC1.K4 USOC1.K9 USOC1.K14 USOC1.K22 USOC1.K32 USOC1.K36 USOC1.K50 USOC1.L13 USOC1.L19 USOC1.L27 USOC1.L35 USOC1.M19 USOC1.M26 USOC1.M27 USOC1.M28 USOC1.M34 USOC1.M35 USOC1.M38 USOC1.M47 USOC1.M51 USOC1.N1 USOC1.N16 USOC1.N38 USOC1.N51 USOC1.P4 USOC1.P9 USOC1.P13 USOC1.P16 USOC1.P19 USOC1.P20 USOC1.P24 USOC1.P32 USOC1.P35 USOC1.P38 USOC1.P47 USOC1.P52 USOC1.T40 USOC1.U1 USOC1.U3 USOC1.U5 USOC1.U6 USOC1.U8 USOC1.U9 USOC1.U11 USOC1.U12 USOC1.U14 USOC1.U16 USOC1.U21 USOC1.U30 USOC1.U32 USOC1.U40 USOC1.U42 USOC1.U43 USOC1.U45 USOC1.U46 USOC1.U48 USOC1.U49 USOC1.U51 USOC1.U53 USOC1.V7 USOC1.V12 USOC1.V16 USOC1.V19 USOC1.V21 USOC1.V35 USOC1.V40 USOC1.V44 USOC1.V51 USOC1.Y7 USOC1.Y9 USOC1.Y10 USOC1.Y14 USOC1.Y16 USOC1.Y21 USOC1.Y25 USOC1.Y33 USOC1.Y41 USOC1.Y44 UT2.4 UT2.33 UX1.2 UX2.3 YC1.2 YC1.4 YL2.2 YL2.4
GNDA: CA1.2 CA2.2 CA23.1 CA33.2 CA38.2 CA39.2 CA40.2 CA51.2 CA61.2 CA62.1 CA63.1 CA71.2 CA74.2 JHP.5 QA5.1 QA5.4 QA6.1 QA6.4 RA29.1 RA30.1 RA31.1 RA32.1 RA83.2 RA84.2 RA153.1 RA154.1 UA1.25 UA1.38
V1: PQ708.2 PQ709.6 PQ713.6 PR702.2 PR714.2
V18: CR4.2 UR1.24
VCCST_PG_EC: CE35.1 DE1.2 T209.1(TP-1) UE1.123
VDD_1.35VP: PC213.1 PR201.1 PR203.2 PU200.11
VDDP_LDO: PC714.1 PR709.1 PR710.1 PU700.21
VIN: PC3.1 PC4.1 PL1.2 PQ704.5 PQ704.6 PQ704.7 PQ704.8 PR12.1 PR14.2 PR702.1 PR706.2 PR707.1 PR711.2 PR730.1
65W/90W#: T220.1(TP-1) UE1.117
+A_VCC: RA10.2 RA12.2 RA28.2
+A_VCC_R: RA28.1 UA1.20
+BIOS_SPI: CC21.1 RC36.1 RC37.1 RC38.1 RC99.1 UC8.8
+CHGRTC: DC3.2 JP12.2
+CODEC_AVDD2: CA61.1 RA8.2 RA9.2 UA1.9 UA1.40
+DDR_SOC_VREF: CC2.1 RC6.2 RC7.2 USOC1.AF44
+DIMM1_VREF_CA: C1078.1 R1029.2 R1030.2 RD4.2
+DIMM1_VREF_DQ: C1076.1 CD1.1 CD2.1 JDIMM1.1 R1027.2 R1028.2
+EC_VCCA: CE7.1 LE1.2 PR10.1 UE1.67
+FAN_POWER: CE22.1 CE23.1 JFAN.1 UE3.3
+INV_PWR_SRC: JLVDS.39 JLVDS.40 RV301.2
+INV_PWR_SRC_R: CX5.1 QX2.1 QX2.2 QX2.5 QX2.6 RV301.1
+LAN_IO: CG3.1 CL15.1 CL19.1 CX51.1 JP6.2 RL28.2 RL34.1 RL36.1 RL38.2 UG1.8 UL1.23 UL1.32
+LAN_IO_UL3: JP6.1 UL3.1
+LAN_VDD: CL20.1 CL22.1 CL26.1 CL34.1 CL35.1 UL1.8 UL1.30
+LCDVDD: CX2.1 CX3.1 LX1.1 UX1.1
+LCDVDD_CONN: CX8.1 CX11.1 JLVDS.24 JLVDS.25 LX1.2 RV31.1 RV300.2
+LCDVDD_CONN_R: QX1.2 RV31.2 RV32.2
+MIC2-VREFO: RA53.2 RA1109.2 UA1.29
+RTCBATT: JBATT1.1 RC33.2 RG1.1
+RTCBATT_R: DC3.3 RC33.1
+RTCVCC: CC23.1 DC3.1 RA5.1 RA12.1 RC34.1 RC35.1 RG2.1 USOC1.P22
+SOC_VCC: CD32.1 PC901.2 PC903.2 PC905.2 PC907.2 PC909.1 PC911.1 PC929.2 PC930.2 PC931.2 PC932.2 PC933.2 PC934.2 PL501.4 RC56.1 USOC1.AA27 USOC1.AA29 USOC1.AA30 USOC1.AC27 USOC1.AC29 USOC1.AC30 USOC1.AD27 USOC1.AD29 USOC1.AD30 USOC1.AF27 USOC1.AF29 USOC1.AG27 USOC1.AG29 USOC1.AG30 USOC1.P26 USOC1.P27 USOC1.U27 USOC1.U29 USOC1.V27 USOC1.V29 USOC1.V30 USOC1.Y27 USOC1.Y29 USOC1.Y30
+SOC_VNN: PC913.2 PC914.2 PC915.2 PC916.2 PC917.1 PC918.1 PC919.1 PC920.2 PC921.2 PC922.2 PC923.2 PC924.2 PC925.2 PC926.2 PC927.2 PC928.2 PL500.4 RC55.1 USOC1.AA24 USOC1.AC22 USOC1.AC24 USOC1.AD22 USOC1.AD24 USOC1.AF22 USOC1.AF24 USOC1.AG22 USOC1.AG24 USOC1.AJ22 USOC1.AJ24 USOC1.AK22 USOC1.AK24 USOC1.AK25 USOC1.AK27 USOC1.AK29 USOC1.AK30 USOC1.AK32 USOC1.AM22
+SW_LX: LT3.2 RT331.2 UT2.12
+SWR_V12: CT9.1 CT10.1 CT11.1 CT12.1 LT3.1 RT331.1 UT2.7 UT2.11 UT2.27
+VDISPLAY_VCC: CX21.1 CX22.1 FX1.1 JHDMI.18 RP15.1 RP15.2
ACIN: CE18.2 DC1.1 PR16.1 PR710.2 PR712.1 PR716.1 PU700.13 UE1.110
ACIN_65W: T221.1(TP-1) UE1.108
ACOFF: PQ713.5 PR718.1 UE1.27
ACSETIN: PC712.2 PR711.1 PR715.2 PU700.2
AD_BID0: CE8.1 RE3.1 RE5.2 UE1.75
ADP_I: PC725.2 PR11.1 PR722.1 UE1.65
ADPIN: PC1.1 PC2.1 PJPDC1.4 PJPDC1.5 PL1.1
AUD_HP_OUT_L_CN: CA39.1 DA10.3 JHP.1 LA8.1
AUD_HP_OUT_R_CN: CA33.1 DA10.2 JHP.2 LA9.1
B+: CX4.1 PJP200.1 PL102.1 PL502.2 PL701.1 PQ706.1 PQ706.2 PQ706.3 PR700.4 QX2.4 RS6.2 RX2.1
B+_1.35VP: PC203.1 PC204.1 PC205.1 PC206.1 PJP200.2 PQ201.5 PR205.1
BAT_ALERT: PBATT1.3 PD1.2
BATT+: PC5.1 PC717.1 PC718.1 PC719.1 PC720.1 PL4.1 PQ706.5 PQ706.6 PQ706.7 PQ706.8 PR720.4 PR726.2
BATT++: PBATT1.8 PBATT1.9 PC6.1 PL4.2
BATT_LOW_LED#: RD17.1 UE1.93
BATT_PRS: PBATT1.5 PC11.1 PD1.3 PR6.1
BATT_TEMP: CE9.2 PC708.1 PQ710.2 PQ710.5 PQ713.2 PR6.2 PR7.1 UE1.63
BEEP#: DA8.2 UE1.23
BKOFF#: UE1.105 UX2.2
BOOT1: PR531.1 PU500.16
BOOT_1.35VP: PR200.2 PU200.18
BOOTG: PR511.1 PU500.26
BST: PR713.2 PU700.25
BST_1.35VP: PC207.1 PR200.1
BST_3V: PR107.2 PU100.9
BST_5V: PR108.1 PU100.17
BST_CHGA: PC713.1 PR713.1
BT_LED#: JMINI.46 QD19.3 RD47.2 RD49.1 UD1.2
BT_ON#: RM13.2 RP54.2 USOC1.AT28
CAPS_LED: JKB.1 UE1.91
CE_EN: RX18.1 UE1.17
CE_EN_R: JLVDS.18 RX18.2 RX20.1
CHG: PL700.2 PR720.1
CHG_B+: PC702.1 PC703.1 PC704.1 PC705.1 PL701.2 PQ701.5 PQ701.6 PQ701.7 PQ701.8
CIICSCL: RT9.2 UT2.9
CIICSDA: RT11.2 UT2.10
CLK_PCIE_LAN: UL1.15 USOC1.AF4
CLK_PCIE_LAN#: UL1.16 USOC1.AF6
CLK_PCIE_WLAN: JMINI.13 USOC1.AF7
CLK_PCIE_WLAN#: JMINI.11 USOC1.AF9
CLK_SMB: PBATT1.7 PD2.3 PR8.1
CLK_X1: UG1.1
CLK_X2: UG1.16
CLR_CMOS: CLRP1.1 R1088.1 R1089.1
CPU_B+: PC501.1 PC508.1 PC509.1 PC510.1 PC519.1 PC521.1 PC522.1 PL502.1 PQ501.2 PQ501.3 PQ501.4 PQ501.10 PQ503.2 PQ503.3 PQ503.4 PQ503.10
CPU_DETECT#: CE33.1 RE11.1 T215.1(TP-1) UE1.127
CPU_DPB_CTRLCLK_R: JHDMI.15 Q57.1 RP15.8
CPU_DPB_CTRLDAT_R: JHDMI.16 Q58.1 RP15.7
CPU_EDP_AUX#_C: CX44.2 UT2.1
CPU_EDP_AUX_C: CX43.2 UT2.2
CPU_EDP_N0_C: CX46.2 UT2.6
CPU_EDP_P0_C: CX42.2 UT2.5
CRT_DDC_CLK: R379.1 USOC1.BC1
CRT_DDC_DATA: R380.1 USOC1.BC2
CS1: PR105.1 PU100.1
CS2: PR104.2 PU100.5
CS_1.35VP: PR201.2 PU200.13
CSCL: QX6.4 RP56.2 RT9.1 RT21.1
CSDA: QX6.1 RP56.1 RT11.1 RT22.1
CSIN: PR700.3 PR705.1
CSIP: PR700.2 PR704.1
DAT_SMB: PBATT1.6 PD2.2 PR9.1
DBC_EN: RX19.1 UE1.25
DBC_EN_R: JLVDS.21 RX19.2 RX23.1
DBG_UART_RXD: T107.1(TP-1) USOC1.BC16
DBG_UART_TXD: T106.1(TP-1) USOC1.BD14
DCIN: PC711.1 PR707.2 PU700.22
DDI0_RCOMPN: RC9.1 USOC1.AK13
DDI0_RCOMPP: RC9.2 USOC1.AK12
DDI1_ENABLE: RC8.1 USOC1.P30
DDI1_PWM: RC67.1 UC4.2 USOC1.M30
DDR_A_BS0: JDIMM1.109 USOC1.K47
DDR_A_BS1: JDIMM1.108 USOC1.K44
DDR_A_BS2: JDIMM1.79 USOC1.D52
DDR_A_CAS#: JDIMM1.115 USOC1.M44
DDR_A_CKE0: JDIMM1.73 USOC1.C47
DDR_A_CKE2: JDIMM1.74 USOC1.F44
DDR_A_CLK0: JDIMM1.101 USOC1.M50
DDR_A_CLK0#: JDIMM1.103 USOC1.M48
DDR_A_CLK2: JDIMM1.102 USOC1.P50
DDR_A_CLK2#: JDIMM1.104 USOC1.P48
DDR_A_CS0#: JDIMM1.114 USOC1.P44
DDR_A_CS2#: JDIMM1.121 USOC1.P45
DDR_A_D0: JDIMM1.5 USOC1.M36
DDR_A_D1: JDIMM1.7 USOC1.J36
DDR_A_D2: JDIMM1.15 USOC1.P40
DDR_A_D3: JDIMM1.17 USOC1.M40
DDR_A_D4: JDIMM1.4 USOC1.P36
DDR_A_D5: JDIMM1.6 USOC1.N36
DDR_A_D6: JDIMM1.16 USOC1.K40
DDR_A_D7: JDIMM1.18 USOC1.K42
DDR_A_D8: JDIMM1.21 USOC1.B32
DDR_A_D9: JDIMM1.23 USOC1.C32
DDR_A_D10: JDIMM1.33 USOC1.C36
DDR_A_D11: JDIMM1.35 USOC1.A37
DDR_A_D12: JDIMM1.22 USOC1.C33
DDR_A_D13: JDIMM1.24 USOC1.A33
DDR_A_D14: JDIMM1.34 USOC1.C37
DDR_A_D15: JDIMM1.36 USOC1.B38
DDR_A_D16: JDIMM1.39 USOC1.F36
DDR_A_D17: JDIMM1.41 USOC1.G38
DDR_A_D18: JDIMM1.51 USOC1.F42
DDR_A_D19: JDIMM1.53 USOC1.J42
DDR_A_D20: JDIMM1.40 USOC1.G40
DDR_A_D21: JDIMM1.42 USOC1.C38
DDR_A_D22: JDIMM1.50 USOC1.G44
DDR_A_D23: JDIMM1.52 USOC1.D42
DDR_A_D24: JDIMM1.57 USOC1.A41
DDR_A_D25: JDIMM1.59 USOC1.C41
DDR_A_D26: JDIMM1.67 USOC1.A45
DDR_A_D27: JDIMM1.69 USOC1.B46
DDR_A_D28: JDIMM1.56 USOC1.C40
DDR_A_D29: JDIMM1.58 USOC1.B40
DDR_A_D30: JDIMM1.68 USOC1.B48
DDR_A_D31: JDIMM1.70 USOC1.B47
DDR_A_D32: JDIMM1.129 USOC1.K52
DDR_A_D33: JDIMM1.131 USOC1.K51
DDR_A_D34: JDIMM1.141 USOC1.T52
DDR_A_D35: JDIMM1.143 USOC1.T51
DDR_A_D36: JDIMM1.130 USOC1.L51
DDR_A_D37: JDIMM1.132 USOC1.L53
DDR_A_D38: JDIMM1.140 USOC1.R51
DDR_A_D39: JDIMM1.142 USOC1.R53
DDR_A_D40: JDIMM1.147 USOC1.T47
DDR_A_D41: JDIMM1.149 USOC1.T45
DDR_A_D42: JDIMM1.157 USOC1.Y40
DDR_A_D43: JDIMM1.159 USOC1.V41
DDR_A_D44: JDIMM1.146 USOC1.T48
DDR_A_D45: JDIMM1.148 USOC1.T50
DDR_A_D46: JDIMM1.158 USOC1.Y42
DDR_A_D47: JDIMM1.160 USOC1.AB40
DDR_A_D48: JDIMM1.163 USOC1.V45
DDR_A_D49: JDIMM1.165 USOC1.V47
DDR_A_D50: JDIMM1.175 USOC1.AD48
DDR_A_D51: JDIMM1.177 USOC1.AD50
DDR_A_D52: JDIMM1.164 USOC1.V48
DDR_A_D53: JDIMM1.166 USOC1.V50
DDR_A_D54: JDIMM1.174 USOC1.AB44
DDR_A_D55: JDIMM1.176 USOC1.Y45
DDR_A_D56: JDIMM1.181 USOC1.V52
DDR_A_D57: JDIMM1.183 USOC1.W51
DDR_A_D58: JDIMM1.191 USOC1.AC53
DDR_A_D59: JDIMM1.193 USOC1.AC51
DDR_A_D60: JDIMM1.180 USOC1.W53
DDR_A_D61: JDIMM1.182 USOC1.Y51
DDR_A_D62: JDIMM1.192 USOC1.AD52
DDR_A_D63: JDIMM1.194 USOC1.AD51
DDR_A_DM0: JDIMM1.11 USOC1.G36
DDR_A_DM1: JDIMM1.28 USOC1.B36
DDR_A_DM2: JDIMM1.46 USOC1.F38
DDR_A_DM3: JDIMM1.63 USOC1.B42
DDR_A_DM4: JDIMM1.136 USOC1.P51
DDR_A_DM5: JDIMM1.153 USOC1.V42
DDR_A_DM6: JDIMM1.170 USOC1.Y50
DDR_A_DM7: JDIMM1.187 USOC1.Y52
DDR_A_DQS0: JDIMM1.12 USOC1.J38
DDR_A_DQS1: JDIMM1.29 USOC1.C35
DDR_A_DQS2: JDIMM1.47 USOC1.D40
DDR_A_DQS3: JDIMM1.64 USOC1.B44
DDR_A_DQS4: JDIMM1.137 USOC1.N53
DDR_A_DQS5: JDIMM1.154 USOC1.T42
DDR_A_DQS6: JDIMM1.171 USOC1.Y47
DDR_A_DQS7: JDIMM1.188 USOC1.AB52
DDR_A_DQS#0: JDIMM1.10 USOC1.K38
DDR_A_DQS#1: JDIMM1.27 USOC1.B34
DDR_A_DQS#2: JDIMM1.45 USOC1.F40
DDR_A_DQS#3: JDIMM1.62 USOC1.C43
DDR_A_DQS#4: JDIMM1.135 USOC1.M52
DDR_A_DQS#5: JDIMM1.152 USOC1.T44
DDR_A_DQS#6: JDIMM1.169 USOC1.Y48
DDR_A_DQS#7: JDIMM1.186 USOC1.AA51
DDR_A_MA0: JDIMM1.98 USOC1.K45
DDR_A_MA1: JDIMM1.97 USOC1.H47
DDR_A_MA2: JDIMM1.96 USOC1.L41
DDR_A_MA3: JDIMM1.95 USOC1.H44
DDR_A_MA4: JDIMM1.92 USOC1.H50
DDR_A_MA5: JDIMM1.91 USOC1.G53
DDR_A_MA6: JDIMM1.90 USOC1.H49
DDR_A_MA7: JDIMM1.86 USOC1.D50
DDR_A_MA8: JDIMM1.89 USOC1.G52
DDR_A_MA9: JDIMM1.85 USOC1.E52
DDR_A_MA10: JDIMM1.107 USOC1.K48
DDR_A_MA11: JDIMM1.84 USOC1.E51
DDR_A_MA12: JDIMM1.83 USOC1.F47
DDR_A_MA13: JDIMM1.119 USOC1.J51
DDR_A_MA14: JDIMM1.80 USOC1.B49
DDR_A_MA15: JDIMM1.78 USOC1.B50
DDR_A_ODT0: RD8.2 USOC1.T41
DDR_A_ODT2: RD9.2 USOC1.P42
DDR_A_RAS#: JDIMM1.110 USOC1.M45
DDR_A_RST#: CD3.1 JDIMM1.30 RD5.1
DDR_A_RST#_CPU: RD3.2 RD5.2 USOC1.P41
DDR_A_WE#: JDIMM1.113 USOC1.H51
DDR_CORE_PWROK: CC1.1 CC19.1 RC30.2 UC7.4 USOC1.AB42
DDR_PWROK: PR210.2 PU200.10 USOC1.AD42
DDR_RCOMP0: RC3.2 USOC1.AD44
DDR_RCOMP1: RC4.2 USOC1.AF45
DDR_RCOMP2: RC5.2 USOC1.AD45
DDR_TERMN0: RC1.2 USOC1.AF42
DDR_TERMN1: RC2.2 USOC1.AH42
DEVSLP0: RC53.2 RS8.1 UC10.4
DEVSLP_SOC: UC10.2 USOC1.AY14
DH_1.35VP: PQ201.4 PU200.17
DH_CHG: PQ701.4 PU700.24
DISPOFF#: DX1.1 JLVDS.37 RX9.1
DL_1.35VP: PQ203.4 PU200.15
DL_CHG: PQ703.4 PU700.20
DRAM_VDD_S4_CLK: CC27.1 CC28.1 RC54.1 USOC1.AD38 USOC1.AF38
EC_ENVDD: RX8.2 UE1.71
EC_LID_OUT#: U62.2 UE1.101
EC_MUTE#: RA7.1 UA1.47 UE1.83
EC_ON: PR115.1 UE1.112
EC_RSMRST#: CC14.1 CC54.1 JDB1.10 RC26.1 UE1.100 USOC1.B10
EC_RST#: CE11.1 RE8.1 UE1.37
EC_RX: JMINI.51 RM13.1 UE1.31
EC_SCI#: R489.2 U66.2 UE1.20
EC_SMB_CK1: PR8.2 PR717.1 RP36.4 UE1.77
EC_SMB_CK2: JDIMM1.202 JTP.5 QC3.1 QX6.3 R432.2 RE15.1 RP36.2 RT21.2
EC_SMB_CK2_EC: RE15.2 UE1.79
EC_SMB_CK2_R: JMINI.30 R432.1
EC_SMB_DA1: PR9.2 PR719.1 RP36.3 UE1.78
EC_SMB_DA2: JDIMM1.200 JTP.6 QC4.1 QX6.6 R434.2 RE16.1 RP36.1 RT22.2
EC_SMB_DA2_EC: RE16.2 UE1.80
EC_SMB_DA2_R: JMINI.32 R434.1
EC_SMI#: R488.2 U65.2 UE1.15
EC_SPI_CLK_R: RE20.1 UE1.126
EC_SPI_CS0#: RE21.1 UE1.128
EC_SPI_MISO_1: RE19.1 UE1.120
EC_SPI_MOSI_1: RE17.1 UE1.119
EC_TX: JMINI.49 RM11.2 UE1.30
ECAGND: CE7.2 CE9.1 LE2.2 PC7.2 PH1.2 PR20.2 UE1.69
EDID_CLK: JLVDS.34 RP56.3 UT2.29
EDID_DATA: JLVDS.35 RP56.4 UT2.28
EDP_BIA_PWM: R378.2 RX36.1 UC4.4 UT2.16
EDP_CPU_AUX: CX43.1 RT18.1 USOC1.AK3
EDP_CPU_AUX#: CX44.1 RT17.2 USOC1.AK2
EDP_CPU_HPD: Q2309.6 R377.2 USOC1.K30
EDP_CPU_LANE_N0: CX46.1 USOC1.AG1
EDP_CPU_LANE_P0: CX42.1 USOC1.AG3
EDP_HPD: Q2309.2 RT16.1 UT2.32
EN_0.675VSP: PC215.1 PR208.2 PU200.7
EN_1.35VP: PC214.1 PR207.2 PU200.8
EN_3V: PR113.1 PU100.6
EN_5V: PR112.1 PU100.20
EN_5V3V: PC118.1 PR112.2 PR113.2 PR114.2 PR115.2 PR116.1
EN_DFAN1: UE1.70 UE3.4
EN_INVPWR: RV32.1 UE1.68
ENBAKL: RT14.2 UE1.76
ENVDD_R: RX7.1 RX8.1 UX1.3
ERP_LOT6: PC8.1 PQ3.2 PR16.2 PR21.1 UE1.73
FAN_SPEED1: CE24.1 CE29.1 JFAN.2 RE50.2 UE1.28
FB_1.0VALWP: PC310.2 PR307.2 PR309.1 PU301.6
FB_1.05VSP: PC301.2 PR302.2 PR304.1 PU300.6
FB_1.35VP: PR204.1 PR206.1 PU200.6
FB_3V: PC106.2 PR100.2 PR102.2 PU100.4
FB_5V: PC107.1 PR101.1 PR103.1 PU100.2
FB_+1.8VSP: PC401.2 PR402.2 PR404.1 PU400.6
GCLK_VRTC: CG5.1 RG1.2 UG1.10
GPIO_NC12: T98.1(TP-1) USOC1.B30
GPIO_NC13: RC10.2 RC11.1 USOC1.A29
GPIO_NC14: T97.1(TP-1) USOC1.C29
GPIO_RCOMP: RC32.2 USOC1.N26
GPIO_S0_SC_56: RC43.2 RC48.1 USOC1.BC12
GPIO_S0_SC_63: RC16.2 USOC1.BA30
GPIO_S0_SC_65: QC1.1 RC17.2 USOC1.BC30
GPIO_S0_SC_92: T110.1(TP-1) USOC1.BH30
GPIO_S0_SC_93: T111.1(TP-1) USOC1.BG30
GPIO_S5_14: RP65.3 USOC1.J20
GPIO_S5_17: T104.1(TP-1) USOC1.J24
GPO: RL36.2 UL1.26
H_PROCHOT#: CC8.2 CE19.1 PQ4.3 PQ4.6 Q50.1 RC15.1 RE13.2 RE44.2 UE2.4 USOC1.C24
HDA_BIT_CLK: RC66.2 USOC1.BJ21
HDA_BITCLK_AUDIO: CC7.1 R2355.1 RC66.1 UA1.6
HDA_RCOMP: RC14.1 USOC1.BF20
HDA_RST#: RC71.2 USOC1.BG22
HDA_RST_AUDIO#: RA6.1 RC71.1 UA1.11
HDA_SDIN0: RA130.1 USOC1.BG19
HDA_SDOUT: RC70.2 USOC1.BG20
HDA_SDOUT_AUDIO: RC70.1 UA1.5
HDA_SYNC: RC69.2 USOC1.BH20
HDA_SYNC_AUDIO: RC69.1 UA1.10
HDMI_CLK+: CX13.2 USOC1.AP3
HDMI_CLK-: CX12.2 USOC1.AP2
HDMI_DDCCLK: Q57.3 RP15.6 USOC1.C28
HDMI_DDCDATA: Q58.3 RP15.5 USOC1.C26
HDMI_GND: Q14.3 R1071.2 R1072.2 R1073.2 R1074.2 R1075.2 R1076.2 R1077.2 R1078.2
HDMI_HPD#: Q14.6 R376.2 USOC1.D27
HDMI_HPLUG: JHDMI.19 Q14.2 R121.1
HDMI_TX0+: CX15.2 USOC1.AR3
HDMI_TX0-: CX14.2 USOC1.AR1
HDMI_TX1+: CX17.2 USOC1.AT2
HDMI_TX1-: CX16.2 USOC1.AT3
HDMI_TX2+: CX19.2 USOC1.AV3
HDMI_TX2-: CX18.2 USOC1.AV2
HPOUT-L: RA55.1 UA1.32
HPOUT-R: RA56.1 UA1.33
HSIC_RCOMP: RC49.2 USOC1.A7
HUB_BUSJ: R1049.2 U58.18
HUB_OVCJ: C1121.1 R1046.2 R1051.2 U58.1
HUB_VBUSM: C1122.2 R1050.2 U58.17
HUB_XIN: U58.4 Y9.3
HUB_XOUT: U58.3 Y9.1
HUB_XRSTJ: R1047.2 U58.16
ICLK_ICOMP: RC23.2 USOC1.AD14
ICLK_RCOMP: RC22.2 USOC1.AD13
ICLK_USB_TERMN: RC42.2 USOC1.F10
ICLK_USB_TERMP: RC41.2 USOC1.D10
ILB_RTC_EXTPAD: CC15.1 USOC1.B8
ILB_RTC_X1: CC18.1 RC31.2 USOC1.C9 YC2.2
ILB_RTC_X2: CC17.1 RC31.1 USOC1.A9 YC2.1
INT-SPK-L+: LA6.1 UA1.42
INT-SPK-L-: LA5.1 UA1.43
INT-SPK-R+: LA4.1 UA1.45
INT-SPK-R-: LA3.1 UA1.44
ISL88731_ICREF: PR727.1 PR729.2 PU700.1
ISL88731_VREF: PR725.2 PR727.2 PU700.3
ISOLATEB: RL33.2 RL35.2 UL1.20
JACK_PLUG#: JHP.4 RA1.2 RA3.1 RA4.1
JACK_SENSE#: QA5.3 RA4.2 RA34.2 RA51.2
JHDD_P10: JHDD.10 RS7.2 RS8.2
KB_CAPS_PWR: JKB.4 RE60.2
KB_LED_PWM: T192.1(TP-1) UE1.21
KB_RST#: U61.2 UE1.2
KSI0: JKB.22 UE1.55
KSI1: JKB.24 UE1.56
KSI2: JKB.26 UE1.57
KSI3: JKB.23 UE1.58
KSI4: JKB.27 UE1.59
KSI5: JKB.25 UE1.60
KSI6: JKB.28 UE1.61
KSI7: JKB.29 UE1.62
KSO0: JKB.13 UE1.39
KSO1: JKB.15 UE1.40
KSO2: JKB.14 UE1.41
KSO3: JKB.16 UE1.42
KSO4: JKB.20 UE1.43
KSO5: JKB.21 UE1.44
KSO6: JKB.18 UE1.45
KSO7: JKB.19 UE1.46
KSO8: JKB.17 UE1.47
KSO9: JKB.7 UE1.48
KSO10: JKB.5 UE1.49
KSO11: JKB.6 UE1.50
KSO12: JKB.12 UE1.51
KSO13: JKB.9 UE1.52
KSO14: JKB.8 UE1.53
KSO15: JKB.10 UE1.54
KSO16: JKB.11 UE1.81
LAN_CLKREQ#: RP63.1 UL1.12 USOC1.BG3
LAN_X1_R: RG5.1 UG1.6
LCD_TEST: JLVDS.33 UE1.72
LG_3V: PQ103.4 PU100.11
LG_5V: PQ104.4 PU100.15
LGATE1: PQ503.8 PU500.19
LGATEG: PQ501.8 PU500.23
LID_SW#: CE30.1 JPWR.2 RE71.2 UE1.115
LINE1-L: CA67.1 UA1.22
LINE1-R: CA68.1 UA1.21
LINE1-VREFO-L: RA165.1 UA1.31
LINE1-VREFO-R: RA166.1 UA1.30
LINE-IN-L: LA8.2 RA55.2 RA80.2 RA83.1 RA165.2
LINE-IN-R: LA9.2 RA56.2 RA82.2 RA84.1 RA166.2
LPC_AD0: UE1.10 USOC1.BH16
LPC_AD1: UE1.8 USOC1.BJ17
LPC_AD2: UE1.7 USOC1.BJ13
LPC_AD3: UE1.5 USOC1.BG14
LPC_CLK_0: CC25.1 RC51.2 USOC1.BG15
LPC_CLK_1: CC26.1 RC52.2 USOC1.BH14
LPC_CLK_EC: R2354.2 RC51.1 UE1.12
LPC_CLKRUN#: RC60.2 RX4.1 USOC1.BG16
LPC_FRAME#: UE1.4 USOC1.BG17
LPC_RCOMP: RC50.2 USOC1.BF18
LS_OE: RP65.4
LVDS_A0+: JLVDS.2 UT2.25
LVDS_A0-: JLVDS.1 UT2.26
LVDS_A1+: JLVDS.5 UT2.23
LVDS_A1-: JLVDS.4 UT2.24
LVDS_A2+: JLVDS.8 UT2.21
LVDS_A2-: JLVDS.7 UT2.22
LVDS_ACLK+: JLVDS.11 UT2.19
LVDS_ACLK-: JLVDS.10 UT2.20
LX_1.0VALWP: PL301.1 PR306.1 PU301.3
LX_1.05VSP: PL300.1 PR301.1 PU300.3
LX_3V: PC112.1 PL100.2 PQ101.1 PQ101.2 PQ101.3 PQ103.5 PR109.1 PU100.8
LX_5V: PC113.2 PL101.1 PQ102.1 PQ102.2 PQ102.3 PQ104.5 PR110.1 PU100.18
LX_+1.8VSP: PL400.1 PR401.1 PU400.3
LX_CHG: PC713.2 PL700.1 PQ701.1 PQ701.2 PQ701.3 PQ703.5 PQ703.6 PQ703.7 PQ703.8 PR721.1 PU700.23
M_ODT0: JDIMM1.116 RD8.1
M_ODT1: JDIMM1.120 RD9.1
MCT0: RL19.1 TL1.14
MCT1: RL20.1 TL1.11
MDI0+: TL1.8 UL1.1
MDI0-: TL1.7 UL1.2
MDI1+: TL1.2 UL1.4
MDI1-: TL1.1 UL1.5
MDO0+: JLAN.1 TL1.9
MDO0-: JLAN.2 TL1.10
MDO1+: JLAN.3 TL1.15
MDO1-: JLAN.6 TL1.16
ME_SUS_PWR_ACK: T204.1(TP-1) UE1.34
MIC1-L: CA74.1 UA1.19
MIC_CLK: CA22.1 JLVDS.30 LA1.2
MIC_CLK_C: LA1.1 UA1.3
MIC_DATA: JLVDS.32 UA1.2
MIC_IN: LA7.2 QA6.3 RA53.1 UA1.18
MIC_IN_R: CA38.1 DA12.3 JHP.3 LA7.1
MIIC_SCL: RT2.1 RT3.2 UT2.31
MIIC_SDA: RT12.2 RT20.1 UT2.30
MMC1_RCOMP: RC57.1 USOC1.AY18
MS_BS: JREAD.15 UR1.22
MS_CLK_SD_WP: CR5.1 JREAD.5 JREAD.22 RR3.2
MS_CLK_SD_WP_R: RR3.1 UR1.8
MS_D0: JREAD.12 UR1.16
MS_D1_SD_D3: JREAD.3 JREAD.13 UR1.20
MS_D2_SD_CLK: CR6.1 JREAD.10 JREAD.14 RR2.2
MS_D2_SD_CLK_R: RR2.1 UR1.15
MS_D3: JREAD.7 UR1.12
MS_INS#: CR10.1 JREAD.8 UR1.9
NTC: PR523.1 PU500.7
NTC_1: PH502.1 PR523.2 PR529.1
NTCG: PR515.2 PU500.1
NTCG_1: PH501.2 PR514.2 PR515.1
